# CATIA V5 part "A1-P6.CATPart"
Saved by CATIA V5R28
Part number: Part6
Source: Unknown
Bounding box of the stored display mesh (mm): x -3 to 3, y -2.954 to 2.954, z -20 to 20
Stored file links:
  E:\TP Catia - Documents\Additional Exercise\Contrôle\Problem-3-Section-J\A1-P6.CATPart
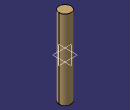
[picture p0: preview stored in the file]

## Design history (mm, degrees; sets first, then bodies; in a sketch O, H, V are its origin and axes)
Body1 (main body)
  Solid1 "Corps principal": solid without history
